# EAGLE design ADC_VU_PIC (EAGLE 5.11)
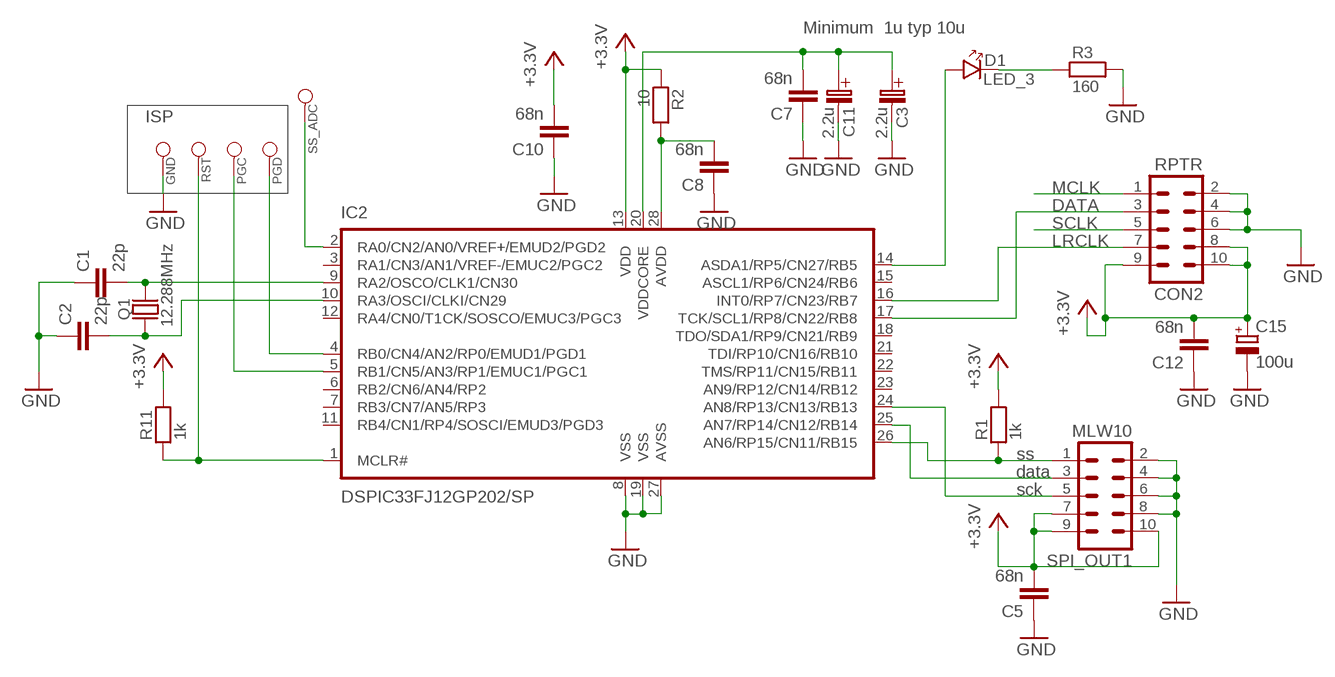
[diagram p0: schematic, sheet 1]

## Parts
C1  22p  C-EUC1206  [C1206]
C2  22p  C-EUC1206  [C1206]
C3  2.2u  C-ELEKTROLYT_2  [C-EL_2]
C5  68n  C-EUC1206  [C1206]
C7  68n  C-EUC1206  [C1206]
C8  68n  C-EUC1206  [C1206]
C10  68n  C-EUC1206  [C1206]
C11  2.2u  C-ELEKTROLYT_2  [C-EL_2]
C12  68n  C-EUC1206  [C1206]
C15  100u  CPOL-EUE2.5-7  [E2,5-7]
CON2  RPTR  MLW10  [MLW10G]
D1  LED_3  [LED_3]
GND  PAD_1  [PAD_1]
IC2  DSPIC33FJ12GP202/SP  [DIL28-3]
PGC  PAD_1  [PAD_1]
PGD  PAD_1  [PAD_1]
Q1  12.288MHz  Q_HC-49U  [HC-49U]
R1  1k  R_SMD_0805  [0805]
R2  10  R_SMD_0805  [0805]
R3  160  R_SMD_1206  [1206]
R11  1k  R_7,5  [R-7,5]
RST  PAD_1  [PAD_1]
SPI_OUT1  MLW10  [MLW10G]
SS_ADC  PAD_1  [PAD_1]

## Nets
+5V: C5.2 C10.2 C12.2 C15.+ CON2.8 CON2.9 CON2.10 IC2.13(VDD) R1.2 R2.1 R11.2 SPI_OUT1.7 SPI_OUT1.9 SPI_OUT1.10 ; supply symbol labelled +3.3V
GND: C1.1 C2.1 C3.C-(C_EL-) C5.1 C7.1 C8.1 C10.1 C11.C-(C_EL-) C12.1 C15.- CON2.2 CON2.4 CON2.6 GND.1 IC2.8(VSS) IC2.19(VSS) IC2.27(AVSS) R3.2 SPI_OUT1.2 SPI_OUT1.4 SPI_OUT1.6 SPI_OUT1.8
N$1: C1.2 IC2.9(RA2/OSCO/CLK1/CN30) Q1.2
N$2: C2.2 IC2.10(RA3/OSCI/CLKI/CN29) Q1.1
N$3: IC2.1(MCLR#) R11.1 RST.1
N$5: IC2.4(RB0/CN4/AN2/RP0/EMUD1/PGD1) PGD.1
N$7: CON2.7 IC2.16(INT0/RP7/CN23/RB7)
N$11: IC2.5(RB1/CN5/AN3/RP1/EMUC1/PGC1) PGC.1
N$12: D1.A IC2.14(ASDA1/RP5/CN27/RB5)
N$13: C3.C+(C_EL+) C7.2 C11.C+(C_EL+) IC2.20(VDDCORE)
N$14: D1.K R3.1
N$15: C8.2 IC2.28(AVDD) R2.2
N$16: IC2.24(AN8/RP13/CN13/RB13) SPI_OUT1.5
N$17: IC2.2(RA0/CN2/AN0/VREF+/EMUD2/PGD2) SS_ADC.1
N$50: IC2.25(AN7/RP14/CN12/RB14) SPI_OUT1.3
N$53: IC2.26(AN6/RP15/CN11/RB15) R1.1 SPI_OUT1.1
N$56: CON2.1
N$86: CON2.3 IC2.17(TCK/SCL1/RP8/CN22/RB8)
N$90: CON2.5
Unconnected: IC2.3(RA1/CN3/AN1/VREF-/EMUC2/PGC2) IC2.6(RB2/CN6/AN4/RP2) IC2.7(RB3/CN7/AN5/RP3) IC2.11(RB4/CN1/RP4/SOSCI/EMUD3/PGD3) IC2.12(RA4/CN0/T1CK/SOSCO/EMUC3/PGC3) IC2.15(ASCL1/RP6/CN24/RB6) IC2.18(TDO/SDA1/RP9/CN21/RB9) IC2.21(TDI/RP10/CN16/RB10) IC2.22(TMS/RP11/CN15/RB11) IC2.23(AN9/RP12/CN14/RB12)

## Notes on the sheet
- Minimum  1u typ 10u
- ISP
- MCLK
- DATA
- SCLK
- LRCLK
- ss
- data
- sck

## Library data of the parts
C1 C2 C5 C7 C8 C10 C12 = rcl:C-EU: CAPACITOR, European symbol
C3 C11 = #PaJa_22:C-ELEKTROLYT: Kondenzator - elektrolyticky
C15 = rcl:CPOL-EU: POLARIZED CAPACITOR, European symbol
CON2 SPI_OUT1 = #PaJa_21:MLW10: Konektory MLW - vidlice - 10x
D1 = #PaJa_22:LED: LED - jednobarevna
GND PGC PGD RST SS_ADC = #PaJa_21:PAD_1: Pajeci bod - 2,54 mm prumer
IC2 = microchip-dspic:DSPIC33FJ12GP202: dsPIC33 General DSC
Q1 = #PaJa_21:Q_HC-49U: Krystal - 1MHz - 48MHz
R1-R3 R11 = #PaJa_21:R: Rezistor

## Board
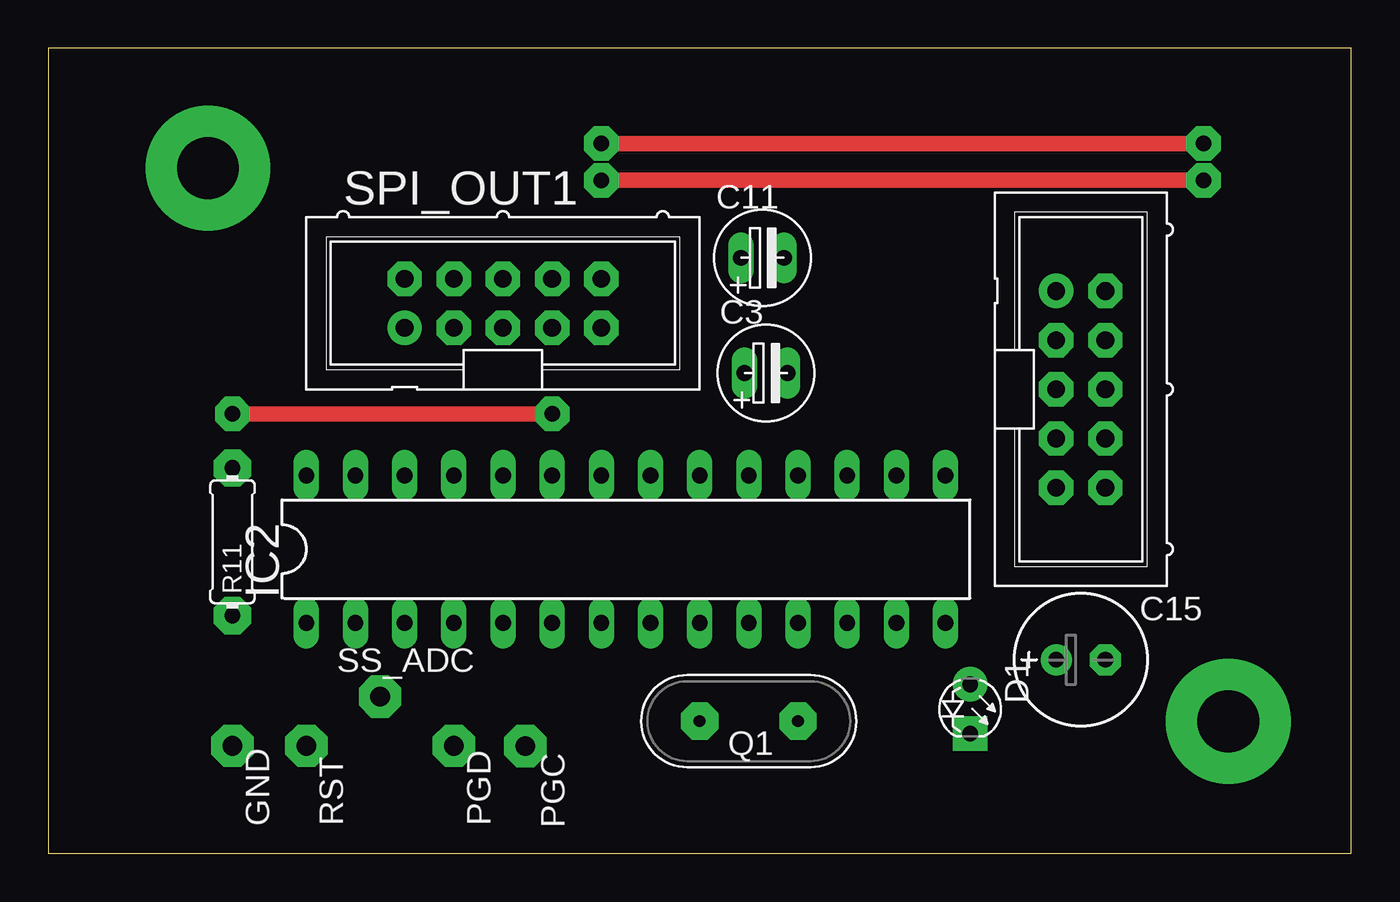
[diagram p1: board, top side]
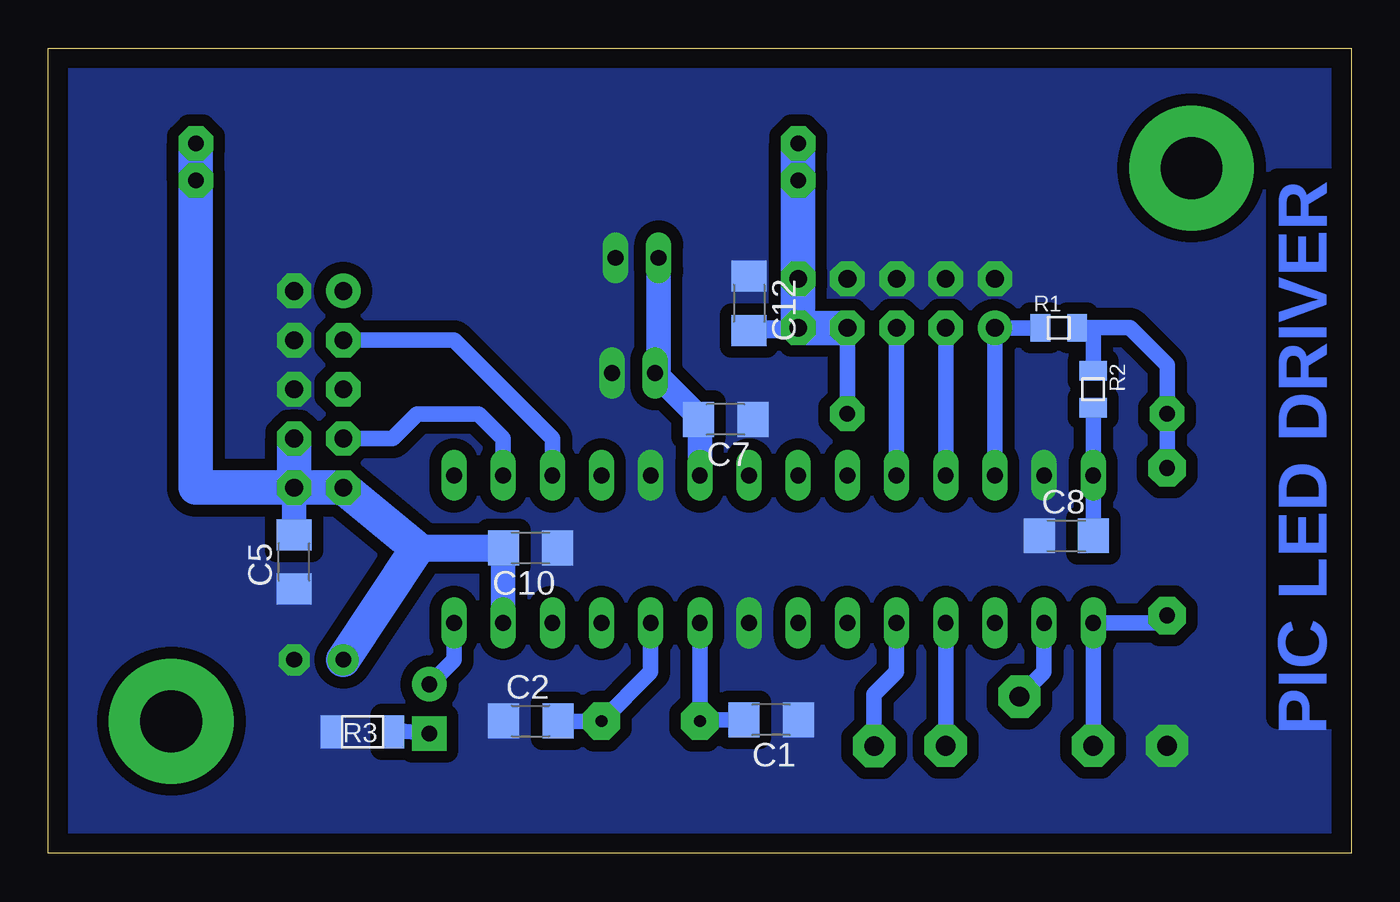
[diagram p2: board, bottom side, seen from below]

Size 67.29 x 41.58 mm. Coordinates in mm from the lower left corner, seen from the top.
Outline: 67.29,41.58 0,41.58 0,0 67.29,0 67.29,41.58
Copper layers (1*16): Top 0.035mm / dielectric 1.5mm / Bottom 0.035mm
Design rules "default *": minimum track width 10mil, minimum drill 24mil, track to track 0.23mm, track to pad 0.23mm, pad to pad 8mil, via to via 8mil, smd to smd 8mil, copper to edge 40mil, drill to drill 8mil, minimum pad ring 10mil, minimum via ring 8mil, stop-mask expansion 4mil, vias tented up to drill 0mil, thermal gap 10mil

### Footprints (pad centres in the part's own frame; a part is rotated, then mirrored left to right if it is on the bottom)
C1206 = smd 1.6 x 1.8: 1 -1.4,0; 2 1.4,0
C-EL_2 = drill 0.813 pad 1.27 long: C+ 0,0; C- 2.223,0
E2,5-7 = drill 0.813 pad 1.6 round: + -1.27,0 | drill 0.813 pad 1.6 octagon: - 1.27,0
MLW10G = drill 0.914 pad 1.778 round: 1 -5.08,-1.27 | drill 0.914 pad 1.778 octagon: 2 -5.08,1.27; 3 -2.54,-1.27; 4 -2.54,1.27; 5 0,-1.27; 6 0,1.27; 7 2.54,-1.27; 8 2.54,1.27; 9 5.08,-1.27; 10 5.08,1.27
LED_3 = drill 0.813 pad 1.778 round: A -1.27,0 | drill 0.813 pad 1.778 square: K 1.27,0
PAD_1 = drill 1.016 pad 2.184 octagon: 1 0,0
DIL28-3 = drill 0.813 long: 1 -16.51,-3.81; 2 -13.97,-3.81; 3 -11.43,-3.81; 4 -8.89,-3.81; 5 -6.35,-3.81; 6 -3.81,-3.81; 7 -1.27,-3.81; 8 1.27,-3.81; 9 3.81,-3.81; 10 6.35,-3.81; 11 8.89,-3.81; 12 11.43,-3.81; 13 13.97,-3.81; 14 16.51,-3.81; 15 16.51,3.81; 16 13.97,3.81; 17 11.43,3.81; 18 8.89,3.81; 19 6.35,3.81; 20 3.81,3.81; 21 1.27,3.81; 22 -1.27,3.81; 23 -3.81,3.81; 24 -6.35,3.81; 25 -8.89,3.81; 26 -11.43,3.81; 27 -13.97,3.81; 28 -16.51,3.81
HC-49U = drill 0.61 pad 1.93 octagon: 1 -2.54,0; 2 2.54,0
0805 = smd 1.016 x 1.422: 1 -0.953,0; 2 0.953,0
1206 = smd 1.143 x 1.702: 1 -1.587,0; 2 1.587,0
R-7,5 = drill 0.813 pad 1.93 octagon: 1 -3.81,0; 2 3.81,0

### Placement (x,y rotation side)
C1  29.96,6.89 180 bottom
C2  42.38,6.84 0 bottom
C3  35.96,24.81 0 top
C5  54.6,15.05 90 bottom
C7  32.31,22.42 180 bottom
C8  14.71,16.4 0 bottom
C10  42.39,15.77 180 bottom
C11  35.77,30.76 0 top
C12  31.1,28.41 270 bottom
C15  53.33,10 0 top
CON2  53.33,23.97 270 top
D1  47.61,7.45 270 top
GND  9.51,5.55 0 top
IC2  29.83,15.71 0 top
PGC  24.64,5.54 0 top
PGD  20.94,5.55 0 top
Q1  36.18,6.82 180 top
R1  15.1,27.15 0 bottom
R2  13.32,23.97 270 bottom
R3  51.06,6.27 180 bottom
R11  9.5,16.09 90 top
RST  13.32,5.55 180 top
SPI_OUT1  23.48,28.41 0 top
SS_ADC  17.13,8.09 0 top

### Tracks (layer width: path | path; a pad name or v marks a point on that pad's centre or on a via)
+5V  (via drill 0.8 pad 1.78)
  Top 0.813: v9.5,22.7 v26.02,22.7 | v28.56,34.76 v59.68,34.76 | v28.56,36.67 v59.68,36.67
  Bottom 0.813: 13.32,27.15 11.42,27.15 9.5,25.23 v9.5,22.7 R11.2 | 13.32,27.15 R1.2 | CON2.8 54.61,21.41 | CON2.10 54.47,18.76 | C10.2 43.8,15.12 | v26.02,22.7 SPI_OUT1.7 | 13.32,27.15 R2.1 | SPI_OUT1.9 30.97,27.14 C12.2 28.69,27.01 SPI_OUT1.9
  Bottom 1.27: 54.61,21.41 C5.2 | 43.8,15.12 IC2.13
  Bottom 1.422: 48.26,15.76 C10.2
  Bottom 1.778: SPI_OUT1.7 SPI_OUT1.9 SPI_OUT1.10 v28.56,34.76 v28.56,36.67 | CON2.10 CON2.9 48.26,15.76 C15.+ | CON2.10 CON2.8 | CON2.10 59.68,18.89 v59.68,34.76 v59.68,36.67
GND
  pour Bottom (isolate 0.61, rank 6, no thermals): 67.93,-0.8 -0.65,-0.8 -0.65,42.38 67.93,42.38
N$1
  Bottom 0.813: IC2.9 | IC2.9 Q1.2 33.64,6.89 C1.2
N$2
  Bottom 0.813: IC2.10 36.18,9.36 Q1.1 40.96,6.82 C2.2
N$3
  Bottom 0.813: RST.1 IC2.1 9.88,11.9 R11.1
N$5
  Bottom 0.813: IC2.4 PGD.1
N$6  (via drill 0.8 pad 1.78)
  other vias: 26.02,22.7
N$7
  Bottom 0.813: CON2.7 49.52,21.43 48.25,22.7 45.07,22.7 43.8,21.43 IC2.16
N$8  (via drill 3.2 pad 6.45)
  other vias: 8.24,35.4
N$10  (via drill 3.2 pad 6.45)
  other vias: 60.94,6.82
N$11
  Bottom 0.813: IC2.5 23.48,9.36 24.64,8.2 PGC.1
N$12
  Bottom 0.813: IC2.14 46.34,10 D1.A
N$13
  Bottom 1.27: IC2.20 33.64,22.35 C7.2 33.71,22.56 C3.C+ 35.77,25 C11.C+
N$14
  Bottom 0.813: D1.K 48.88,6.31 R3.1
N$15
  Bottom 0.813: R2.2 IC2.28 13.31,19.51 C8.2
N$16
  Bottom 0.813: IC2.24 SPI_OUT1.5
N$17
  Bottom 0.813: IC2.2 15.86,9.36 SS_ADC.1
N$50
  Bottom 0.813: IC2.25 SPI_OUT1.3
N$53
  Bottom 0.813: IC2.26 SPI_OUT1.1 R1.1
N$86
  Bottom 0.813: CON2.3 46.34,26.51 41.26,21.43 IC2.17

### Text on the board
Bottom: PIC LED DRIVER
